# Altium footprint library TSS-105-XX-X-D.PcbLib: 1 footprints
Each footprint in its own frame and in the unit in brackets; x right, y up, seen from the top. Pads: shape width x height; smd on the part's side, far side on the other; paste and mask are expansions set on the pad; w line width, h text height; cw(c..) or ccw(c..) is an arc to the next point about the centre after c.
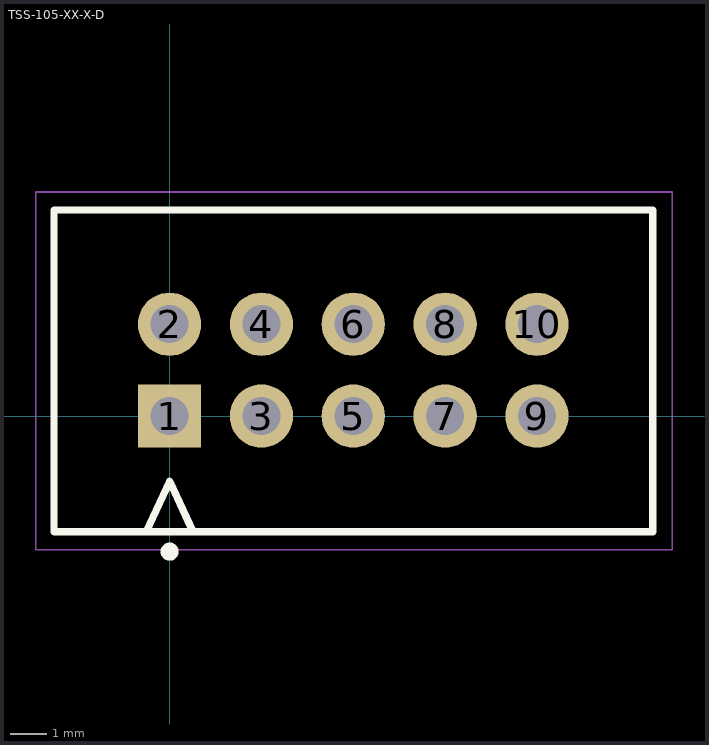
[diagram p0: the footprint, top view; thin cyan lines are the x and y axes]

## TSS-105-XX-X-D [mm] "2.54mm pitch, 10 pin, header; shrouded"
height 8.89
pads (10):
  rect 1.75x1.75 / inner round 1.75 / far side rect 1.75x1.75 hole 1.05 mask+0: 1(0,0)
  round 1.75 hole 1.05 mask+0: 2(0,2.54) 3(2.54,0) 4(2.54,2.54) 5(5.08,0) 6(5.08,2.54) 7(7.62,0) 8(7.62,2.54) 9(10.16,0) 10(10.16,2.54)
Top Overlay:
  circle w0.25: c0,-3.75 r0.125
  lines w0.2: -3.2,-3.2 -3.2,5.7 13.36,5.7 13.36,-3.2 -3.2,-3.2 ; -0.646,-3.2 0.646,-3.2 0,-1.8 -0.646,-3.2
Mechanical 12:
  lines w0.001: -3.2,-3.2 -3.2,5.7 13.36,5.7 13.36,-3.2 -3.2,-3.2
Mechanical 13:
  lines w0.1: -3.2,-3.2 -3.2,5.7 13.36,5.7 13.36,-3.2 -3.2,-3.2 ; -0.646,-3.2 0.646,-3.2 0,-1.8 -0.646,-3.2
  text ".Designator" at 0,0 h1.52
Mechanical 15:
  lines w0.05: -3.7,-3.7 -3.7,6.2 13.9,6.2 13.9,-3.7 -3.7,-3.7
